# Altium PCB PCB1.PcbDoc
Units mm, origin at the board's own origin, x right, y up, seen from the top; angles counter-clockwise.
Board outline 19.7 x 53.48 mm, 2 copper layers (Top Layer, Bottom Layer); 25 components, 25 nets, 112 pads, 0 vias.
Unrouted connection lines stored in the file: 50.
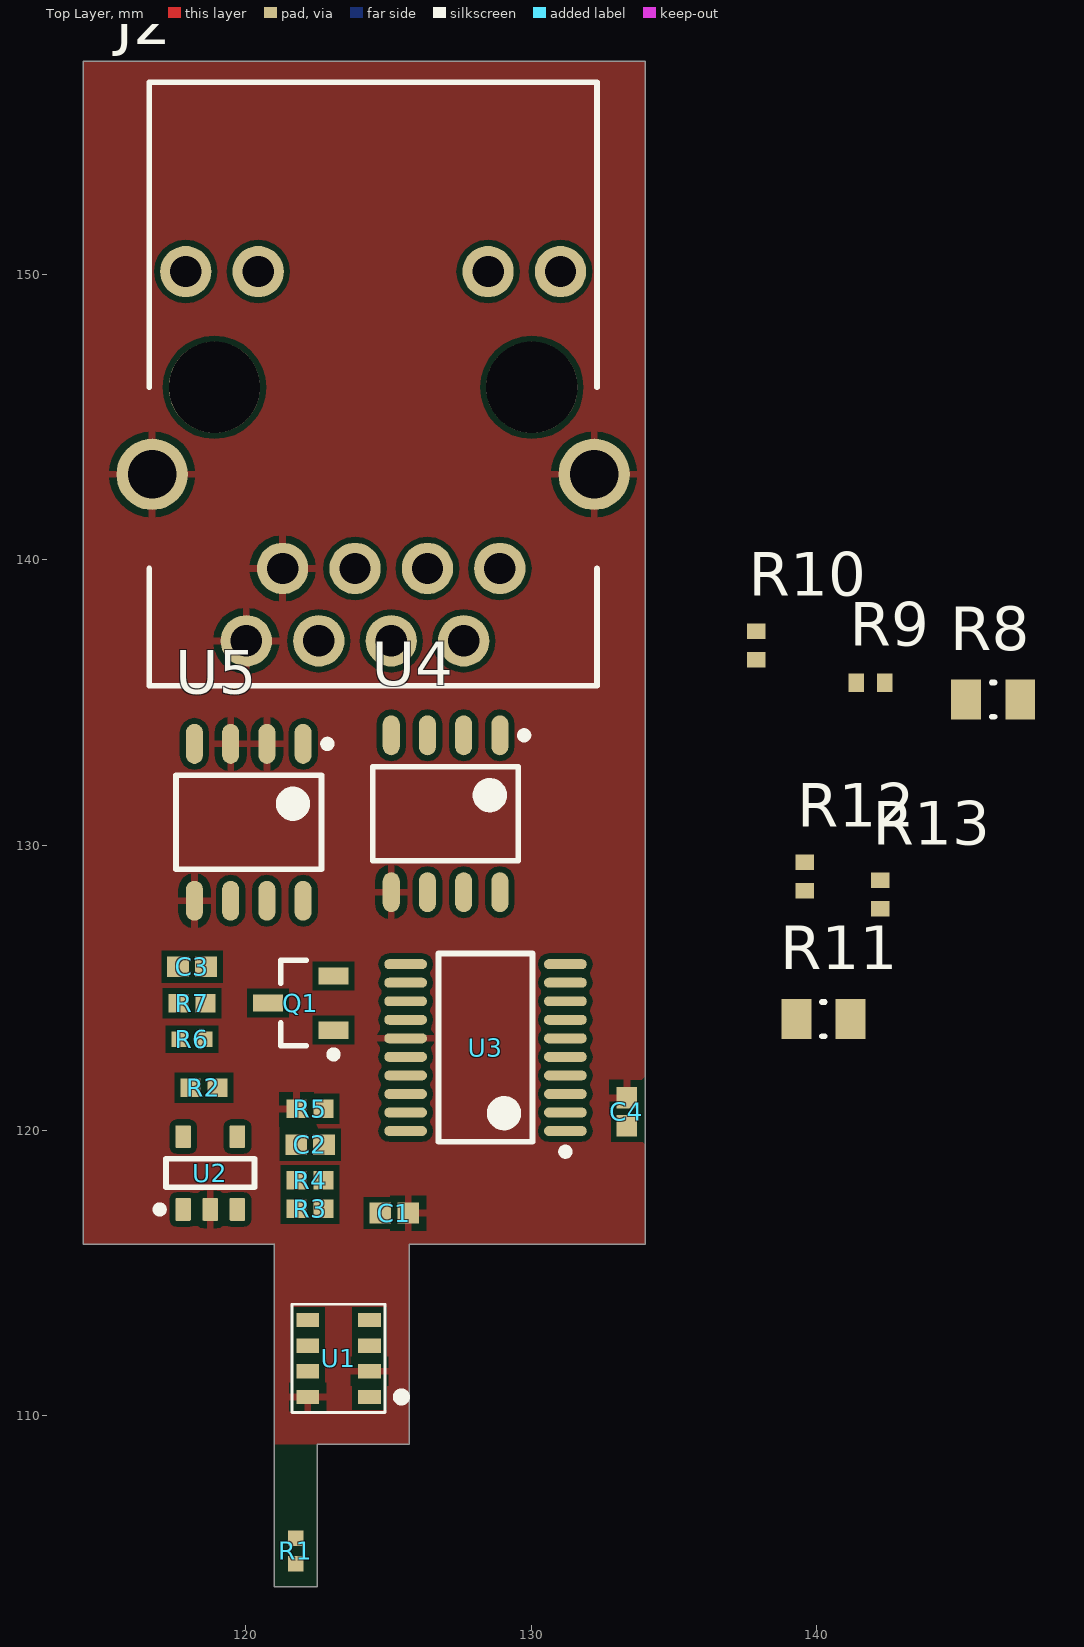
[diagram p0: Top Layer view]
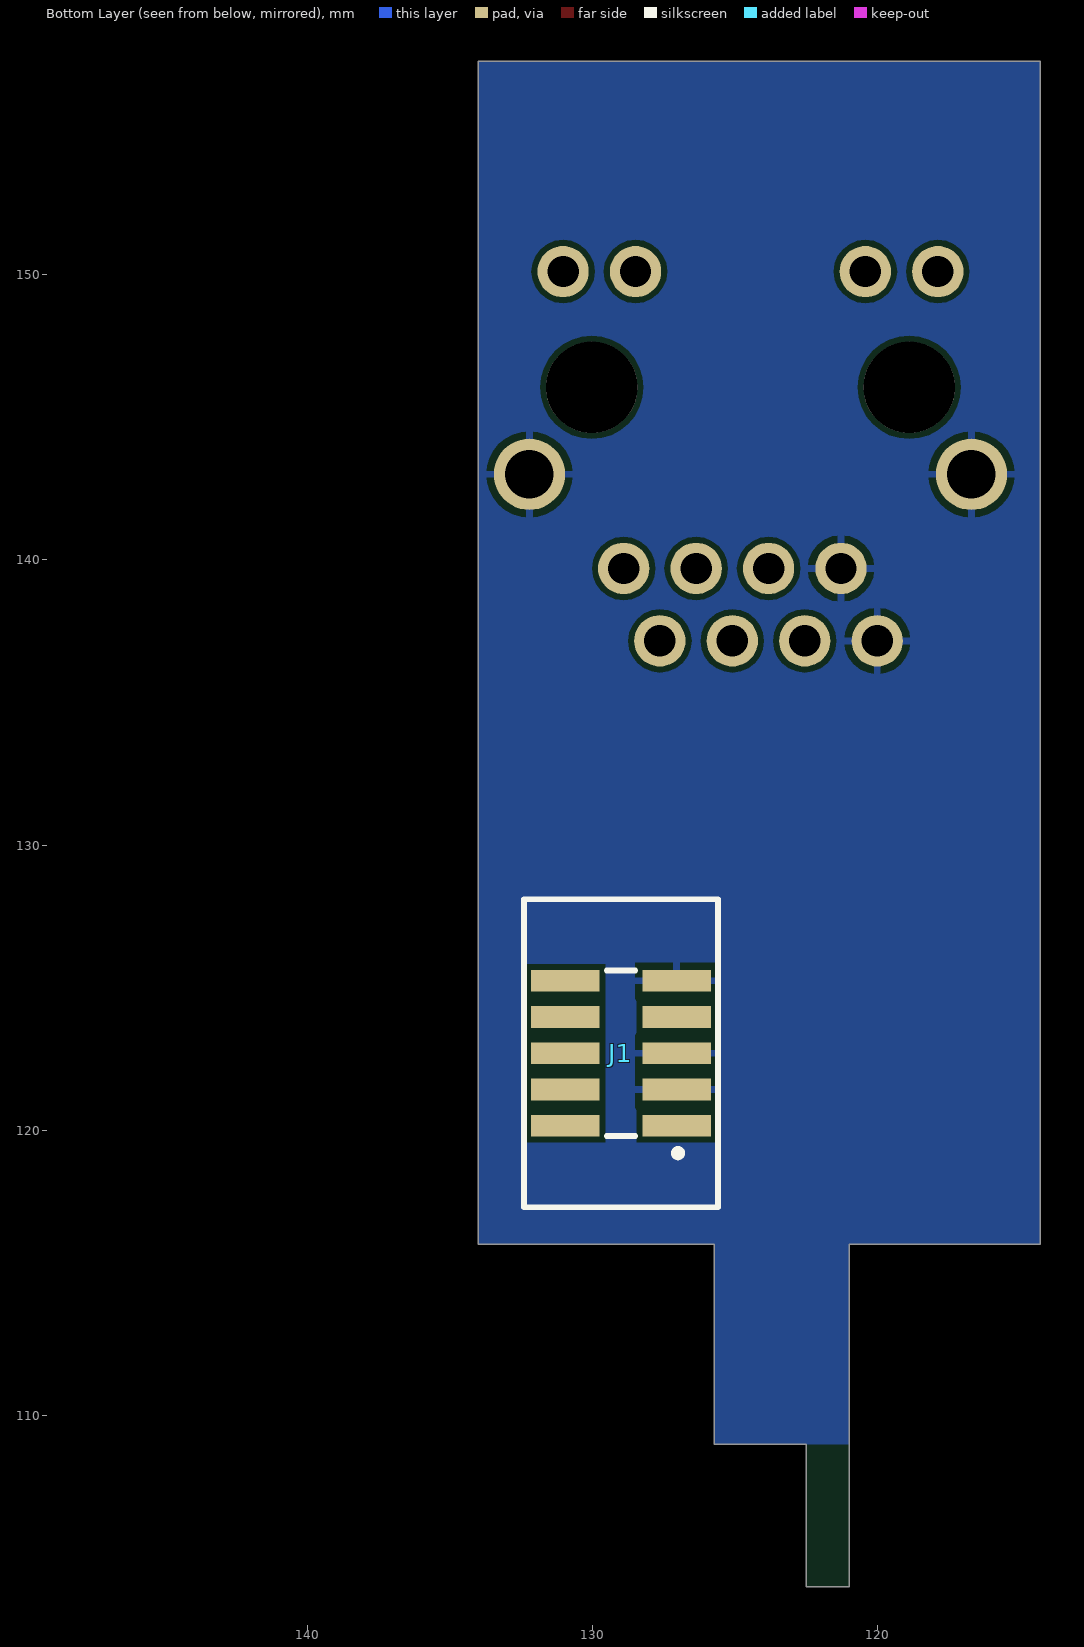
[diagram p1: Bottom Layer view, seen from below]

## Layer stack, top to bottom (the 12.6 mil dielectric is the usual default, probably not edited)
Top Solder: solder mask 0.0102, Solder Resist, Dk 3.5
Top Layer: signal copper 0.0356
Dielectric 1: dielectric 0.32, FR-4, Dk 4.8
Bottom Layer: signal copper 0.0356
Bottom Solder: solder mask 0.0102, Solder Resist, Dk 3.5

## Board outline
121,104 121,116 114.3,116 114.3,157.48 134,157.48 134,116 125.73,116 125.73,109 122.5,109 122.5,104

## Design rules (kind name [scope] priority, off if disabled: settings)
Clearance [All] p1: gap=0.2 ignorepadtopadclearanceinfootprint=FALSE
PolygonConnect [All] p1: connectstyle=Relief reliefconductorwidth=0.254 reliefentries=4 polygonreliefangle="90 Angle" airgapwidth=0.254
RoomDefinition Sheet1 [InComponentClass('Sheet1')] p1: confinementstyle=ConfineIn formatcopy=TRUE lockcomponents=FALSE outline 114,100.25 146.25,100.25 146.25,142 114,142
RoutingVias [All] p1: holewidth=0.3 width=0.6 viastyle="Through Hole" minholewidth=0.3 minwidth=0.5 maxholewidth=0.711 maxwidth=1.27
SolderMaskExpansion [All] p1: expansion=0.102 istentingtop=FALSE
Width [All] p1: maxlimit=0.6 minlimit=0.2 preferedwidth=0.4
30 further rules are at their usual default settings.

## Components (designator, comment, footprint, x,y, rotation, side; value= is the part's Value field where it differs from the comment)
C1 "GRM155R71C104KA88D" CAPC1005X55X25ML05T10 125.2,117.1 r180 top
C2 "100nF" CAPC1005X55X25ML05T10 122.25,119.5 r0 top
C3 "1uF" CAPC1005X55X25ML05T10 118.11,125.73 r180 top
C4 "GRM155R71C104KA88D" CAPC1005X55X25ML05T10 133.35,120.65 r270 top
J1 "ARM Cortex JTAG" "1.27mm 2x5 SMD Header - no paste" 129,122.7 r90 bottom
J2 "RJ45_59_8P8C_LED" RJ45_59_8P8C_LED 124.46,146.05 r180 top
Q1 "SMBT2907A" INF-SOT23_N 121.92,124.46 r180 top
R1 "NTC470, B=3380" RESC1005X40X25NL05T05 121.75,105.25 r270 top
R2 "10M 1%" RESC1005X40X25ML05T10 118.525,121.5 r180 top
R3 "2R21 0.1%" RESC1005X40X25ML05T10 122.25,117.25 r180 top
R4 "2K 0.1%" RESC1005X40X25ML05T10 122.25,118.25 r180 top
R5 "75K 0.1%" RESC1005X40X25ML05T10 122.25,120.75 r0 top
R6 "2K 1%" RESC1005X40X25NL05T05 118.11,123.19 r180 top
R7 "100K 1%" RESC1005X40X25ML05T10 118.11,124.46 r180 top
R8 "120R 5% 0805(2012)" RESC0805(2012)_N 146.2,135.1 r180 top value="120.00 Ohm"
R9 "10K 5% 0402(1005)" RESC0402(1005)_N 141.9,135.7 r180 top value="10000.00 Ohm"
R10 "10K 5% 0402(1005)" RESC0402(1005)_N 137.9,137 r270 top value="10000.00 Ohm"
R11 "120R 5% 0805(2012)" RESC0805(2012)_N 140.25,123.9 r180 top value="120.00 Ohm"
R12 "2K2 5% 0402(1005)" RESC0402(1005)_N 139.6,128.9 r270 top value="2200.00 Ohm"
R13 "2K2 5% 0402(1005)" RESC0402(1005)_N 142.24,128.27 r270 top value="2200.00 Ohm"
U1 "HP203B" HP203B 123.25,112 r180 top
U2 "TLV2471IDBVT" DBV0005A_L 118.75,118.5 r90 top
U3 "STM32F030F4P6" STM-TSSOP20_L 128.4,122.9 r180 top
U4 "AZRS3072" SOIC127P600X175-8N 127,131.1 r270 top
U5 "AZRS3072" SOIC127P600X175-8N 120.1,130.8 r270 top

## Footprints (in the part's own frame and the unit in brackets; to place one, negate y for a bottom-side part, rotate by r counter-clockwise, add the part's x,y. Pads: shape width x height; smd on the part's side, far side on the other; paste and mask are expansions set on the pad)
"1.27mm 2x5 SMD Header - no paste" [mm]
  rect 0.76x2.4 smd paste-99: 1(-2.54,-1.95) 2(-2.54,1.95) 3(-1.27,-1.95) 4(-1.27,1.95) 5(0,-1.95) 6(0,1.95) 7(1.27,-1.95) 8(1.27,1.95) 9(2.54,-1.95) 10(2.54,1.95)
  silkscreen extent -5.4,-3.4 5.4,3.4
CAPC1005X55X25ML05T10 [mm] "Chip Capacitor, 2-Leads, Body 1.00x0.50mm, IPC Low Density"
  rect 0.76x0.72 smd: 1(-0.49,0) 2(0.49,0)
  body extent -0.53,-0.28 0.53,0.27, height 0.55
DBV0005A_L [mm] "SOT23, 5-Leads, Body 3.05x1.75mm, Pitch 0.95mm, IPC High Density"
  rrect18% 0.8x0.55 smd: 1(-1.275,0.95) 2(-1.275,0) 3(-1.275,-0.95) 4(1.275,-0.95) 5(1.275,0.95)
  silkscreen extent -1.4,-1.55 0.5,1.9, body extent -1.42,-1.46 1.42,1.46, height 1.08
HP203B [mm] "PRECISION BAROMETER AND ALTIMETER SENSOR"
  rect 0.8x0.5 smd: 1(-1.08,1.35) 2(-1.08,0.45) 3(-1.08,-0.45) 4(-1.08,-1.35) 5(1.08,-1.35) 6(1.08,-0.45) 7(1.08,0.45) 8(1.08,1.35)
  silkscreen extent -2.35,-1.9 1.63,1.9, body extent -1.63,-1.9 1.63,1.9, height 1.2
INF-SOT23_N [mm] "SOT23, 3-Leads, Body 2.9x1.3 mm, Pitch 0.95 mm, IPC Medium Density"
  rect 1.05x0.6 smd: 1(-1.15,0.95) 2(-1.15,-0.95) 3(1.15,0)
  silkscreen extent -1.28,-1.5 0.7,1.92, body extent -0.7,-1.5 0.7,1.5, height 1.1
RESC0402(1005)_N [mm] "Chip Resistor, Body 1.0x0.5mm, IPC Medium Density"
  rect 0.55x0.65 smd: 1(-0.5,0) 2(0.5,0)
  body extent -0.52,-0.27 0.53,0.28, height 0.4
RESC0805(2012)_N [mm] "Chip Resistor, Body 2.0x1.3mm, IPC Medium Density"
  rect 1.05x1.4 smd: 1(-0.95,0) 2(0.95,0)
  silkscreen extent -0.05,-0.6 0.05,0.6, body extent -1.1,-0.67 1.1,0.68, height 0.7
RESC1005X40X25ML05T10 [mm] "Chip Resistor, 2-Leads, Body 1.00x0.50mm, IPC Low Density"
  rect 0.7x0.65 smd: 1(-0.475,0) 2(0.475,0)
  body extent -0.53,-0.27 0.53,0.28, height 0.4
RESC1005X40X25NL05T05 [mm] "Chip Resistor, 2-Leads, Body 1.00x0.50mm, IPC Medium Density"
  rect 0.55x0.55 smd: 1(-0.45,0) 2(0.45,0)
  body extent -0.53,-0.27 0.53,0.28, height 0.4
RJ45_59_8P8C_LED [mm] "Generic RJ49 jack with LED and without magnetics"
  round 1.8 hole 1.1: 1(-4.445,6.35) 2(-3.175,8.89) 3(-1.905,6.35) 4(-0.635,8.89) 5(0.635,6.35) 6(1.905,8.89) 7(3.175,6.35) 8(4.445,8.89) 9(-6.57,-4.06) 10(-4.03,-4.06) 11(4.03,-4.06) 12(6.57,-4.06)
  round 3.2 hole 3.2 unplated: POS1(-5.565,0) POS2(5.565,0)
  round 2.5 hole 1.7: S1(-7.75,3.05) S2(7.75,3.05)
  silkscreen extent -7.85,-10.7 7.85,10.46, body extent -7.85,-10.58 7.85,10.58, height 13.45
SOIC127P600X175-8N [mm] "SOIC, 8-Leads, Body 4.90x3.90mm, Pitch 1.27mm, IPC Medium Density"
  oval 1.4x0.6 smd: 1(-2.75,1.905) 2(-2.75,0.635) 3(-2.75,-0.635) 4(-2.75,-1.905) 5(2.75,-1.905) 6(2.75,-0.635) 7(2.75,0.635) 8(2.75,1.905)
  silkscreen extent -2.87,-2.55 1.65,2.88, body extent -3,-2.55 3,2.55, height 1.75
STM-TSSOP20_L [mm] "SOP, 20-Leads, Body 6.6x4.5mm, Pitch 0.65mm, IPC High Density"
  oval 1.5x0.35 smd: 1(-2.8,2.925) 2(-2.8,2.275) 3(-2.8,1.625) 4(-2.8,0.975) 5(-2.8,0.325) 6(-2.8,-0.325) 7(-2.8,-0.975) 8(-2.8,-1.625) 9(-2.8,-2.275) 10(-2.8,-2.925) 11(2.8,-2.925) 12(2.8,-2.275) 13(2.8,-1.625) 14(2.8,-0.975) 15(2.8,-0.325) 16(2.8,0.325) 17(2.8,0.975) 18(2.8,1.625) 19(2.8,2.275) 20(2.8,2.925)
  silkscreen extent -2.93,-3.3 1.65,3.77, body extent -2.25,-3.3 2.25,3.3, height 1.2

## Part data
C1 C3 C4: library part CMP-2100-03641-1, "Chip Capacitor, 0.1 uF, +/- 10%, 16 V, -55 to 125 degC, 0402 (1005 Metric), RoHS, Tape and Reel", Capacitance=100nF, Case Code (Imperial)=0402, Case Code (Metric)=1005, Dielectric=X7R, Dielectric Material=Ceramic, Insulation Resistance=10GR, Manufacturer=Murata, Max Operating Temperature=125degC, Min Operating Temperature=-55degC, Package Description="2-Pin Surface Mount Device, Body 1 x 0.5 mm", Package Quantity=1, Tolerance=10%, Voltage=16V
C2: library part CMP-2100-03641-1, "Chip Capacitor, 0.1 uF, +/- 10%, 16 V, -55 to 125 degC, 0402 (1005 Metric), RoHS, Tape and Reel", Case Code (Imperial)=0402, Case Code (Metric)=1005, Dielectric=X7R, Dielectric Material=Ceramic, Insulation Resistance=10GR, Manufacturer=Murata, Max Operating Temperature=125degC, Min Operating Temperature=-55degC, Package Description="2-Pin Surface Mount Device, Body 1 x 0.5 mm", Package Quantity=1, Tolerance=10%, Voltage=16V
J1: "Arm Cortex 10-pin JTAG connector", Manufacturer=Unknown/Generic, PartNumber=unknown/Generic
J2: "Generic RJ49 jack with LED and without magnetics", Manufacturer=Unknown/Generic
Q1: library part CMP-1178-00003-1, "PNP Silicon Switching Transistor, 60 V VCEO, 600 mA IC, SOT23, Reel, Green", Manufacturer=Infineon
R1 R6: library part CMP-2002-01187-1, Manufacturer=Panasonic, Part Number=ERT-J0EV474J
R2 R3 R4 R5 R7: library part CMP-2002-07472-1, Manufacturer="Yageo / Phycomp", Part Number=RC0402FR-071KL
R8 R11: library part CMP-1013-00052-1, "120R 0.125W 5% 0805 (2012 Metric)  SMD", Case-EIA=0805, Case-Metric=2012, Power="0.125 W", Tolerance="5 %"
R9 R10: library part CMP-1011-00098-1, "10K 0.063W 5% 0402 (1005 Metric)  SMD", Case-EIA=0402, Case-Metric=1005, Power="0.063 W", Tolerance="5 %"
R12 R13: library part CMP-1011-00082-1, "2K2 0.063W 5% 0402 (1005 Metric)  SMD", Case-EIA=0402, Case-Metric=1005, Power="0.063 W", Tolerance="5 %"
U1: "PRECISION BAROMETER AND ALTIMETER SENSOR", Manufacturer=HopeRF
U2: library part CMP-0271-00230-3, "Single Low-Power Rail-to-Rail Input / Output Operational Amplifier, 2.7 to 6 V, -40 to 125 degC, 5-pin SOT23 (DBV5), Green (RoHS & no Sb/Br)", Manufacturer="Texas Instruments", Total Supply Voltage(Max)(+5V is 5, +/-5V is 10)=6, Total Supply Voltage(Min)(+5V is 5, +/-5V is 10)=2.7
U3: library part CMP-0304-00039-2, "ARM Cortex-M0 32-bit MCU, 16 KB Flash, 4 KB Internal RAM, 15 I/Os, 20-pin TSSOP, -40 to 85 degC, Tube", I/Os (High Current)=15, Operating Frequency(F) (Processor speed) (MHz)=48, Supply Voltage(Vcc) min (V)=2.4
U4 U5: "ESD-Protected, Slew-Rate-Limited, True Fail-Safe 3.3V RS485 Transceiver IC", Manufacturer="Amazing Microelectronic Corp."

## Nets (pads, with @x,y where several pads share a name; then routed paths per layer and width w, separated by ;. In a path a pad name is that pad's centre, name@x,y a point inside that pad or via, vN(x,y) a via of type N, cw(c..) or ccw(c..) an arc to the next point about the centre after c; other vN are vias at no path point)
3.3V: R12.2 R13.2 U4.2 U4.3 U4.8 U5.8
9V: Q1.3 R7.1 U2.5
+3.3V: C1.2 C4.2 J1.1 R9.1 U1.3 U3.5 U3.16
+12V: J2.4 J2.5
\R\S\T: J1.10 R9.2 U3.4
BOOT0: R10.1 U3.1
"Flow Sense": U3.6
GND: C1.1 C4.1 J1.3 J1.5 J1.9 J2.7 J2.8 J2.S1 J2.S2 R1.1 R5.1 R10.2 U1.2 U1.8 U2.2 U3.15 U4.5 U5.2 U5.3 U5.5
I2C1_SCL: R13.1 U3.3
I2C1_SDA: R12.1 U3.2
NetC3_1: C3.1 Q1.2 R3.2 R4.2
NetQ1_1: Q1.1 R6.1
SCL: U1.5
SDA: U1.6
SENSE+: R1.2 R3.1 R7.2 U2.3
SENSE-: C2.2 C3.2 R2.2 R4.1 R5.2 U2.4
SENSOR_RX+: J2.3 R11.1 U5.6
SENSOR_RX-: J2.6 R11.2 U5.7
SENSOR_TX+: J2.1 R8.1 U4.6
SENSOR_TX-: J2.2 R8.2 U4.7
SWCLK: J1.4 U3.20
SWDIO: J1.2 U3.19
USART1_RX: U3.18 U5.1 U5.4
USART1_TX: U3.17 U4.1 U4.4
VFB: C2.1 R2.1 R6.2 U2.1
pads on no net: J1.6 J1.7 J1.8 J2.9 J2.10 J2.11 J2.12 J2.POS1 J2.POS2 U1.1 U1.4 U1.7 U3.7 U3.8 U3.9 U3.10 U3.11 U3.12 U3.13 U3.14

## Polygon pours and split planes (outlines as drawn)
GND on Top Layer "GND_L01_P001" (solid, pour order 1): 133.25,111.5
GND on Top Layer "GND_L01_P000" (solid, pour order 0): 121,109 125.73,109 125.73,116 134,116 134,157.48 114.3,157.48 114.3,116 121,116
GND on Bottom Layer "GND_L02_P002" (solid, pour order 2): 121,109 125.73,109 125.73,116 134,116 134,157.48 114.3,157.48 114.3,116 121,116

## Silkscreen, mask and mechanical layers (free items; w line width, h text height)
Mechanical 1:
  the board outline again, w0.1
Dimensions:
  lines w0.05: 113,94 137,94 ; 113,95 137,95 ; 113,115 137,115 ; 113,116 137,116
  lines w0.1: 109.22,121.92 115.57,121.92 ; 114.3,120.65 115.57,121.92 ; 114.3,123.19 115.57,121.92 ; 120.65,101.6 121.92,102.87 ; 121.92,88.9 121.92,102.87 ; 123.19,101.6 121.92,102.87 ; 127,106.68 127,107.95 ; 128.27,107.95 127,107.95 ; 137.16,97.79 127,107.95
  text "Other components outside tube" at 91.44,120.65 h1.25
  text "Tube cutaway" at 101.6,95.25 h2 r90
  text "Pressure sensor and thermistor inside tube" at 138.43,92.71 h1.25
  text "Thermistor stick should be thin to reduce thermal mass" at 107.95,83.82 h1.25

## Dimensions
134,157.48 to 122.5,104 on Dimensions
134,157.48 to 114.3,157.48 on Dimensions
113,116 to 113,105 on Dimensions
113,116 to 113,94 on Dimensions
